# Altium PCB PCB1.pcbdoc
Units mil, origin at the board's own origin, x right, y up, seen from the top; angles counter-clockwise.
Board outline 1771.65 x 1496.06 mil, 2 copper layers (Top Layer, Bottom Layer); 9 components, 8 nets, 27 pads, 3 vias.
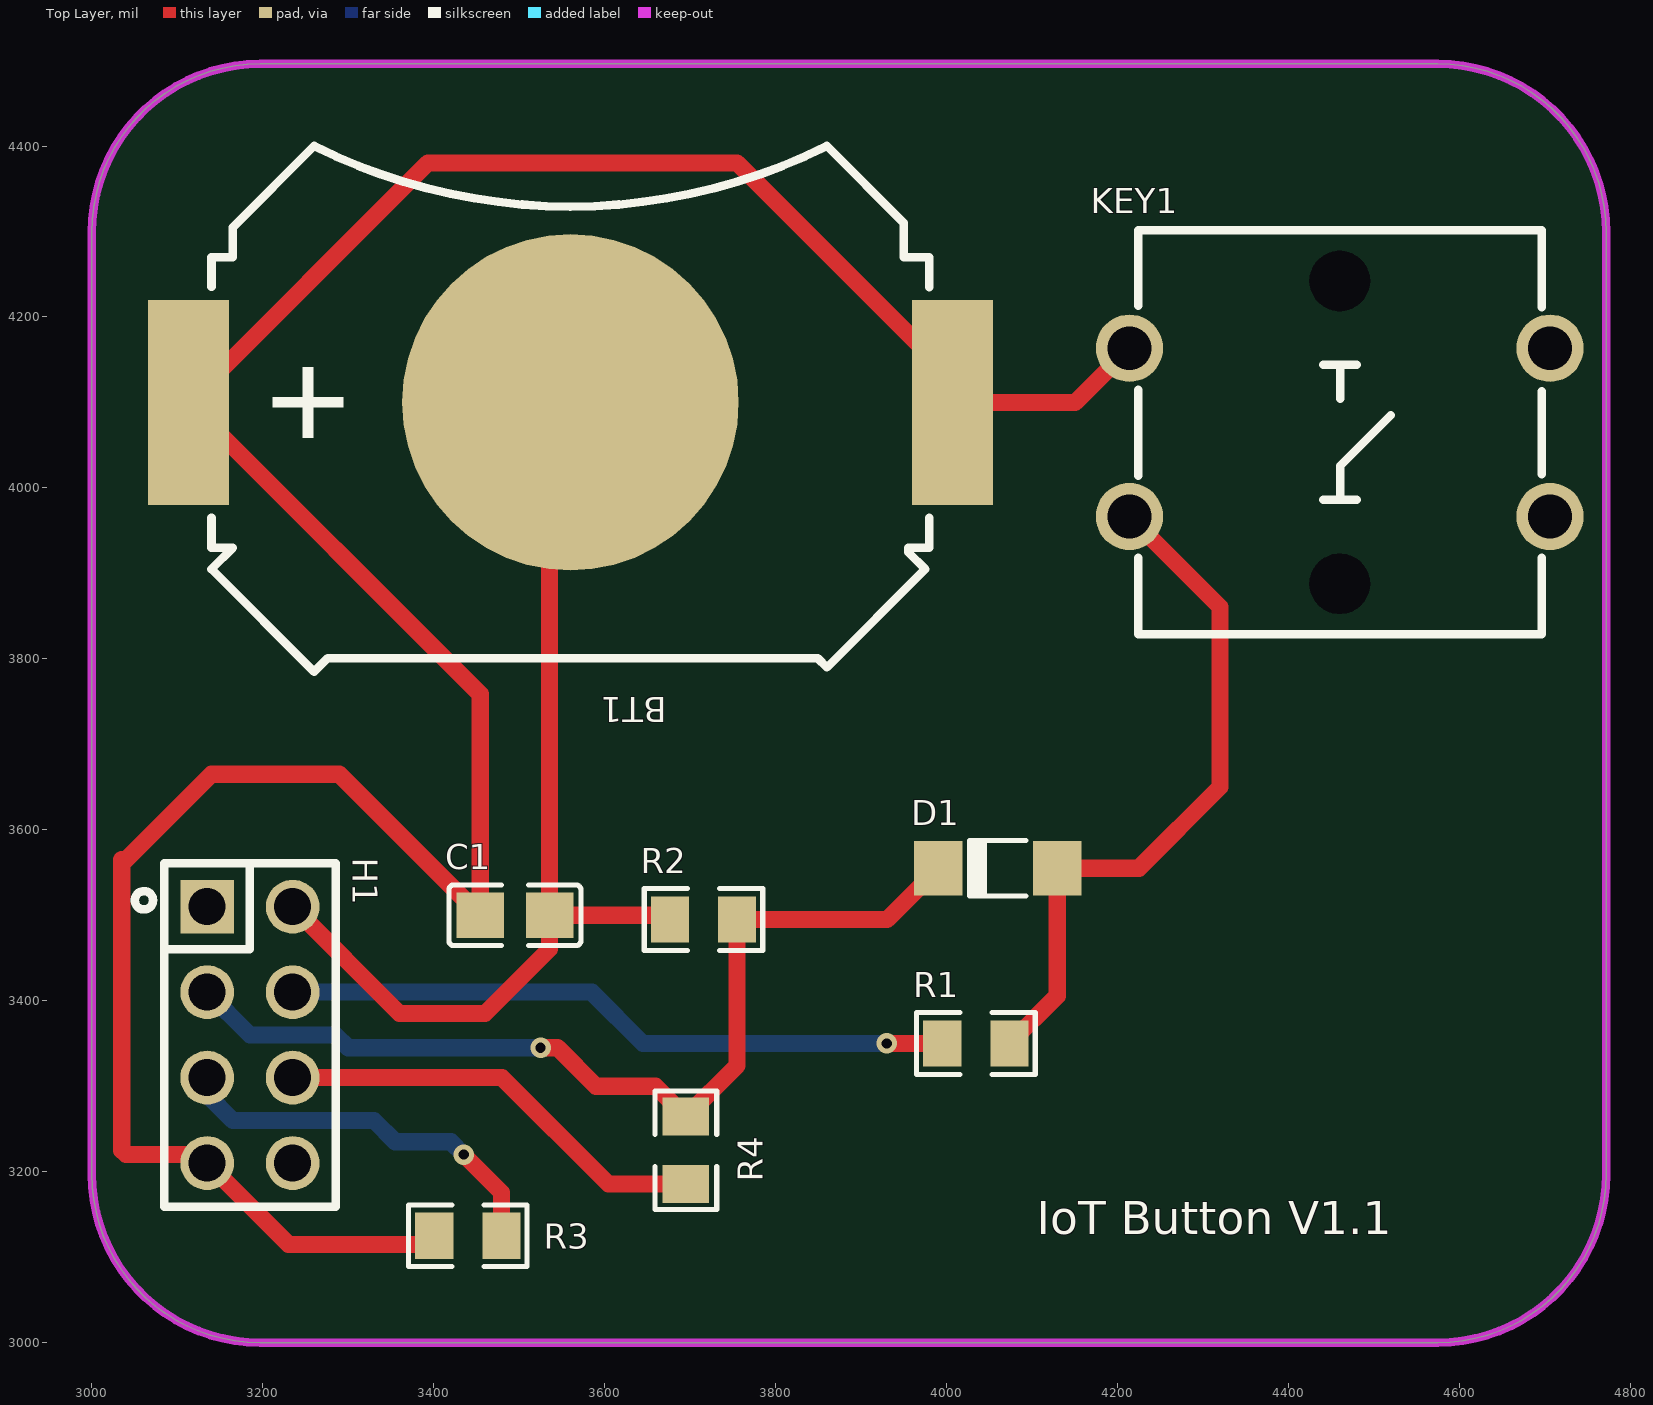
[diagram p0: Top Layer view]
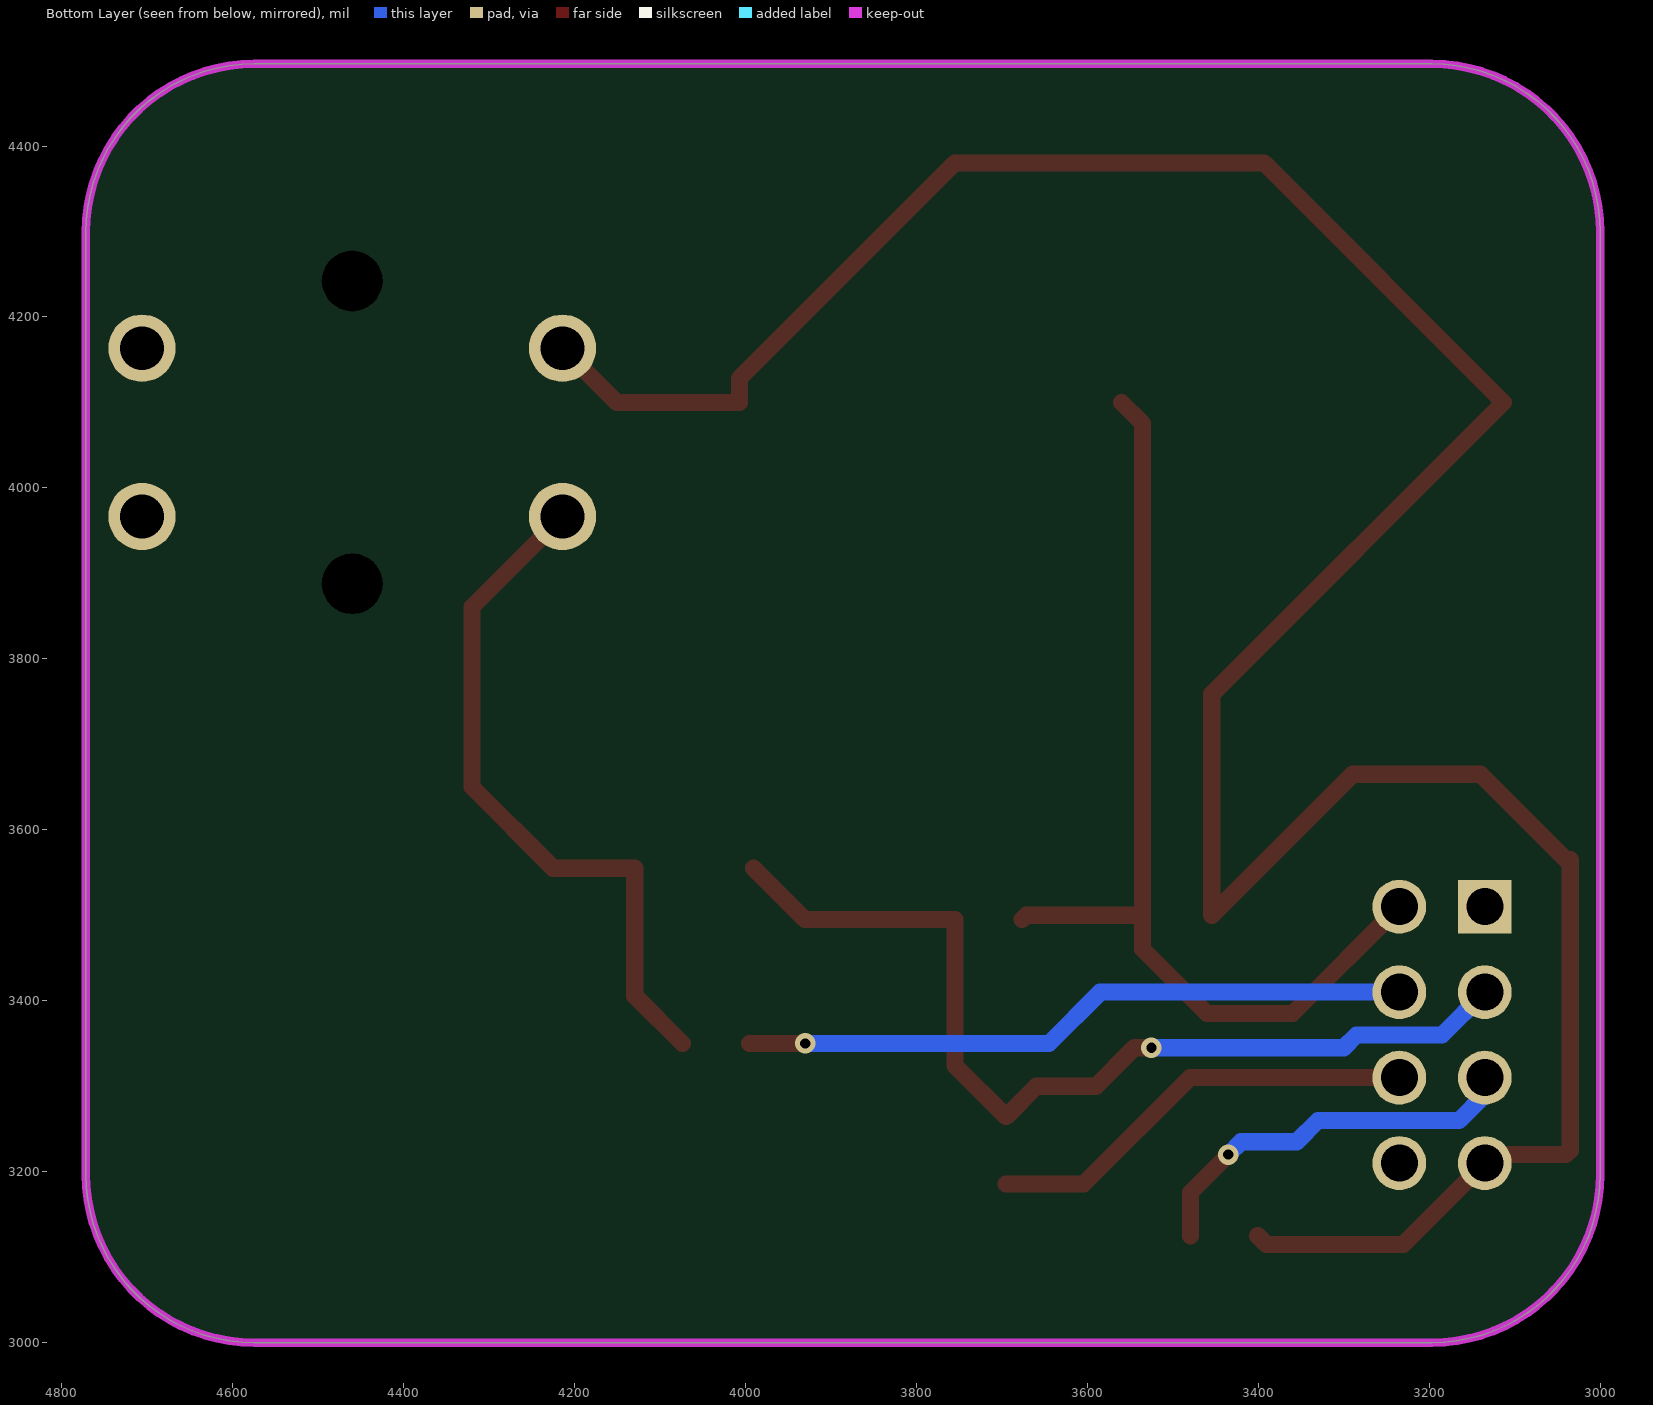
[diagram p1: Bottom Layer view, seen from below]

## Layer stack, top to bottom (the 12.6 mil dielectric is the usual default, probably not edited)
Top Layer: signal copper (thickness not stored)
Dielectric: dielectric 12.6, FR-4, Dk 4.8
Bottom Layer: signal copper (thickness not stored)

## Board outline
3196.85,4496.06 4574.8,4496.06 cw(c4574.8,4299.21) 4771.65,4299.21 4771.65,3196.85 cw(c4574.8,3196.85) 4574.8,3000 3196.85,3000 cw(c3196.85,3196.85) 3000,3196.85 3000,4299.21 cw(c3196.85,4299.21)

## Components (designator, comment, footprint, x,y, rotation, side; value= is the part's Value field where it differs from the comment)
BT1 "MY-2032-12" BAT-SMD_MY-2032-12 3560,4100 r180 top
C1 "GRM21BR60J107ME15L" C0805 3495,3500 r0 top
D1 "LL4148_C2857181" LL-34_L3.4-W1.5-RD 4060,3555 r0 top
H1 "DS1023-2*4SF11" HDR-TH_8P-P2.54-V-F-R2-C4-S2.54-1 3185,3360 r270 top
KEY1 "B3F-4055_C84931" KEY-TH_4P-L12.0-W12.0-P5.00-LS13.4-EH 4460,4065 r0 top
R1 "0805W8F1001T5E" R0805 4034.37,3350 r0 top
R2 "0805W8F1002T5E" R0805 3715.63,3495 r0 top
R3 "0805W8F1002T5E" R0805 3440,3125 r0 top
R4 "0805W8F1001T5E" R0805 3695,3225 r90 top

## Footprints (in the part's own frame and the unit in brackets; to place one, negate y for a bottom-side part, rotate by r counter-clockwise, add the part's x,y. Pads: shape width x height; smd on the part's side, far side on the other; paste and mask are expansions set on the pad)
BAT-SMD_MY-2032-12 [mm]
  rect 2.4x6.1 smd: 1(-11.35,0) 1(11.35,0)
  round 10 smd: 2(0,0)
  silkscreen extent -10.67,-7.62 10.67,8
C0805 [mm]
  rect 1.41x1.35 smd: 1(-1.03,0) 2(1.03,0)
  silkscreen extent -1.96,-0.9 1.96,0.9
HDR-TH_8P-P2.54-V-F-R2-C4-S2.54-1 [mm]
  rect 1.6x1.6 hole 1.1: 1(-3.81,-1.27)
  round 1.6 hole 1.1: 2(-3.81,1.27) 3(-1.27,-1.27) 4(-1.27,1.27) 5(1.27,-1.27) 6(1.27,1.27) 7(3.81,-1.27) 8(3.81,1.27)
  silkscreen extent -5.1,-3.42 5.1,2.55
KEY-TH_4P-L12.0-W12.0-P5.00-LS13.4-EH [mm]
  round 2 hole 1.3: 1(6.25,-2.5) 2(-6.25,-2.5) 3(6.25,2.5) 4(-6.25,2.5)
  Multi-Layer board cut-out: 0.9,4.5 0.811,4.89 0.561,5.204 0.2,5.377 -0.2,5.377 -0.561,5.204 -0.811,4.89 -0.9,4.5 -0.9,4.5 -0.811,4.109 -0.561,3.796 -0.2,3.623 0.2,3.623 0.561,3.796 0.811,4.109 0.9,4.5
  Multi-Layer board cut-out: 0.9,-4.5 0.811,-4.109 0.561,-3.796 0.2,-3.623 -0.2,-3.623 -0.561,-3.796 -0.811,-4.109 -0.9,-4.5 -0.9,-4.5 -0.811,-4.89 -0.561,-5.204 -0.2,-5.377 0.2,-5.377 0.561,-5.204 0.811,-4.89 0.9,-4.5
  silkscreen extent -5.99,-6 6.01,6
LL-34_L3.4-W1.5-RD [mm]
  rect 1.44x1.62 smd: 1(-1.765,0) 2(1.765,0)
  silkscreen extent -0.84,-0.83 0.84,0.83
R0805 [mm]
  rect 1.133x1.377 smd: 1(-1,0) 2(1,0)
  silkscreen extent -1.76,-0.92 1.76,0.92

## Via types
v1: diameter 24, hole 12, Top Layer to Bottom Layer, 3 vias

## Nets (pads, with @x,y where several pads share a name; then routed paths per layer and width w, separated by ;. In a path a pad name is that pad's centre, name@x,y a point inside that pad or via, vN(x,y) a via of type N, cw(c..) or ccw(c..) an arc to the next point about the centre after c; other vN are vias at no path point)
3V3: BT1.1 C1.1 H1.7 KEY1.4 R3.1 | length 3401.4
  Top Layer w20: R3.1 3390.63,3115 3230,3115 H1.7 3125,3220 3040,3220 3035,3225 3035,3565 3040,3565 3140,3665 3289.45,3665 C1.1 3454.45,3758.7 3113.15,4100 3393.15,4380 3755,4380 4006.85,4128.15 4006.85,4100 4150.52,4100 KEY1.4
$1N247: H1.4 R1.1 | length 784.9
  Top Layer w20: v1(3930,3350) R1.1
  Bottom Layer w20: H1.4 3585,3410 3645,3350 v1(3930,3350)
$1N250: H1.6 R4.1 | length 511.5
  Top Layer w20: H1.6 3480,3310 3604.37,3185.63 R4.1
$1N806: D1.2 KEY1.2 R1.2 | length 818.5
  Top Layer w20: R1.2 4129.49,3405.75 D1.2 4225,3555 4320,3650 4320,3860.51 KEY1.2
$1N1520: H1.5 R3.2 | length 462.4
  Top Layer w20: v1(3435,3220) 3479.37,3175.63 R3.2
  Bottom Layer w20: H1.5 3135,3290 3165,3260 3330,3260 3355,3235 3420,3235 v1(3435,3220)
CH_PD: D1.1 H1.3 R2.2 R4.2 | length 1136.2
  Top Layer w20: v1(3525,3345) 3545,3345 3590,3300 3659.37,3300 R4.2 3755,3324.37 R2.2 3930.51,3495 D1.1
  Bottom Layer w20: H1.3 3185,3360 3285,3360 3300,3345 v1(3525,3345)
GND: BT1.2 C1.2 H1.2 R2.1 | length 1176
  Top Layer w20: H1.2 3360,3385 3460,3385 3535.55,3460.55 C1.2 ; BT1.2 3535.55,4075.55 C1.2 ; R2.1 3671.26,3500 C1.2
"": H1.1 H1.8 KEY1.1 KEY1.3

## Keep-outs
Board Outline Layer:
  the board outline again, w10

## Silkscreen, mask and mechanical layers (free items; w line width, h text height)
Top Silkscreen Layer:
  text "IoT Button V1.1" at 4105.65,3126.81 h38.94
